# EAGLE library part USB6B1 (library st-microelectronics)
DATA LINES PROTECTION Source: http://www.st.com/stonline/products/literature/ds/5605.pdf
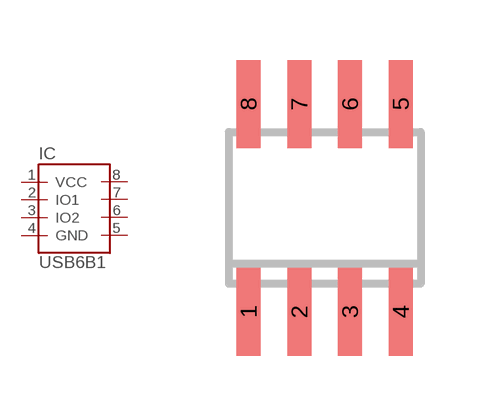
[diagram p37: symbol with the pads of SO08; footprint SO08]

Designator prefix IC

## USB6B1 (MPN: USB6B1; OC_FARNELL: 9804358; OC_NEWARK: 26M4750)  [SO08]
1  VCC  pwr
2  IO1
3  IO2
4  GND  pwr
5  GND  pwr
6  IO2
7  IO1
8  VCC  pwr

## Footprint SO08 (pad centres in mm)
SMALL OUTLINE INTEGRATED CIRCUIT body 3.9 mm/JEDEC MS-012AA
smd 0.6 x 2.2: 1 -1.905,-2.6; 2 -0.635,-2.6; 3 0.635,-2.6; 4 1.905,-2.6; 5 1.905,2.6; 6 0.635,2.6; 7 -0.635,2.6; 8 -1.905,2.6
